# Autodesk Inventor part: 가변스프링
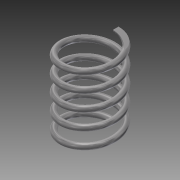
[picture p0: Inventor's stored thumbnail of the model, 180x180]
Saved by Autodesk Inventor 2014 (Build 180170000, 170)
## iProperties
Created: 2018-12
Part Number: 가변스프링
Material: 스테인레스 스틸
Document SubType Name: Modeling
Designer: kh
Density: 8.08 g/cm^3
Appearance: 반연마
Author: kh
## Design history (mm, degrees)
sketch "스케치1"
  geometry: L1 (0, 0)-(9, 0); L2 (9, 0)-(9, 28.5); L3 (9, 28.5)-(0, 28.5); L4 (0, 28.5)-(0, 0); C1 r 1 at (9, 0)
  constraints: 8 end point, 2 parallel, 1 centre point, 1 coincident, 1 horizontal, 1 perpendicular
  dimensions: "d0" = 18 diameter of L2 L4; "d1" = 28.5 distance of L1.end L2.end (derived); "d2" = 2 diameter of C1
feature "코일1" sketch "스케치1" pitch "d3" = 10; turns "d5" = 5; dims "d4" = 28.5 (= d1), "d6" = 0, angle "d7" = 90 deg, angle "d8" = 90 deg, "d9" = 0, "d10" = 0
node "작업 평면1"
feature "분할1"
feature "분할2"
node "솔리드1"
